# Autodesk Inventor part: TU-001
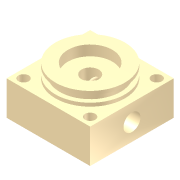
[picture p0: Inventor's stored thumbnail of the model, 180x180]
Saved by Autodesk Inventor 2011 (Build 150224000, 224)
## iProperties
Created: 2008-05
Part Number: TU-001
Document SubType Name: Modeling
Designer: PN
Density: 7.86 g/cm^3
Material: Steel, Mild
Description: Cylinder Head Cover_Back
Mass: 377.701 g
Surface Area: 134.999 cm^2
Volume: 48.0535 cm^3
d32: 6.000 mm
Author: PN
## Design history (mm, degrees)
sketch "Sketch1"
  geometry: L1 (-24.5, 24.5)-(24.5, 24.5); L2 (24.5, 24.5)-(24.5, -24.5); L3 (24.5, -24.5)-(-24.5, -24.5); L4 (-24.5, -24.5)-(-24.5, 24.5); 3 further points
  constraints: 8 end point, 2 midpoint, 2 parallel, 1 horizontal, 1 horizontal alignment, 1 perpendicular, 1 vertical alignment
  dimensions: "Width" = 49 distance of L1.start L1.end; "Height" = 49 distance of L3.end L1.start (= Width)
extrude "Extrusion1" new body sketch "Sketch1" distance "d2" = 20; taper "d3" = 0 deg
sketch "Sketch2"
  geometry: L1 (24.5, 24.5)-(24.5, -24.5) reference; L2 (-24.5, 24.5)-(24.5, 24.5) reference; L3 (-24.5, -24.5)-(-24.5, 24.5) reference; L4 (24.5, -24.5)-(-24.5, -24.5) reference; L5 (19.5, 19.5)-(19.5, -19.5); L6 (19.5, -19.5)-(-19.5, -19.5); L7 (-19.5, -19.5)-(-19.5, 19.5); L8 (-19.5, 19.5)-(19.5, 19.5); 1 further point
  constraints: 8 end point, 3 other
  dimensions: "d4" = 5 distance between parallel lines of L7 L3; "d5" = 39 distance of L5.end L6.end (derived); "d6" = 39 distance of L6.end L7.end (derived)
hole "Hole1" sketch "Sketch2" at (-19.5, -19.5) diameter "d7" = 6; stored, may be unused: countersink angle "d11" = 90 deg, drill point angle "d13" = 118 deg; dims "d8" = 6, "d9" = 4, "d10" = 2, "d12" = 8
pattern_linear "Rectangular Pattern1" dims "d16" = 39 (= d5), "d19" = 39 (= d6)
sketch "Sketch3"
  geometry: L1 (-24.5, 20)-(24.5, 20) reference; L2 (0, 20)-(0, 28); L3 (0, 28)-(20.35, 28); L4 (20.35, 28)-(20.35, 26); L5 (20.35, 26)-(17.8, 26); L6 (17.8, 26)-(17.8, 22); L7 (17.8, 22)-(20.35, 22); L8 (20.35, 22)-(20.35, 20); 1 further point
  constraints: 14 end point, 4 perpendicular, 2 collinear, 2 parallel, 1 midpoint, 1 point on line
  dimensions: "d25" = 8 distance of L2.start L2.end; "d26" = 20.35 distance of L2.end L3.end; "d27" = 2 distance of L3.end L4.end; "d28" = 4 distance of L5.end L6.end; "d29" = 17.8 distance between parallel lines of L6 L2
revolve "Revolution1" sketch "Sketch3" stored, may be unused: angle "d30" = 90 deg
sketch "Sketch4"
  geometry: L1 (0, -20)-(49, -20) reference; L2 (0, 0)-(0, -20) reference; L3 (24.5, -20)-(24.5, -14); 1 further point
  constraints: 2 end point, 1 midpoint, 1 parallel
  dimensions: "d32" = 6 distance of L3.start L3.end
hole "Hole2" diameter "d35" = 10; stored, may be unused: countersink angle "d39" = 90 deg, drill point angle "d41" = 0 deg; dims "d33" = 10, "d34" = 10, "d36" = 6, "d37" = 26, "d38" = 6, "d40" = 18
hole "Hole3" sketch "Sketch4" diameter "d42" = 8; stored, may be unused: countersink angle "d46" = 90 deg, drill point angle "d48" = 118 deg; dims "d43" = 9, "d44" = 26, "d45" = 6, "d47" = 18, "d57" = 0.62479, "d58" = 7.985
sketch "Sketch6"
  geometry: L1 (0, 49)-(0, 0) reference; L2 (0, 49)-(-20, 49) reference; 4 further points
  constraints: 2 midpoint, 1 horizontal alignment, 1 vertical alignment
hole "Hole4" sketch "Sketch6" at (-10, 24.5) diameter "d49" = 10; stored, may be unused: countersink angle "d53" = 90 deg, drill point angle "d55" = 118 deg; dims "d50" = 6, "d51" = 26, "d52" = 6, "d54" = 10
mirror "Mirror1"
workplane "Work Plane1"
body "Solid1"
other parameters: "d56" = 24
